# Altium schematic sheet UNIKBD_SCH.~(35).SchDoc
size A4
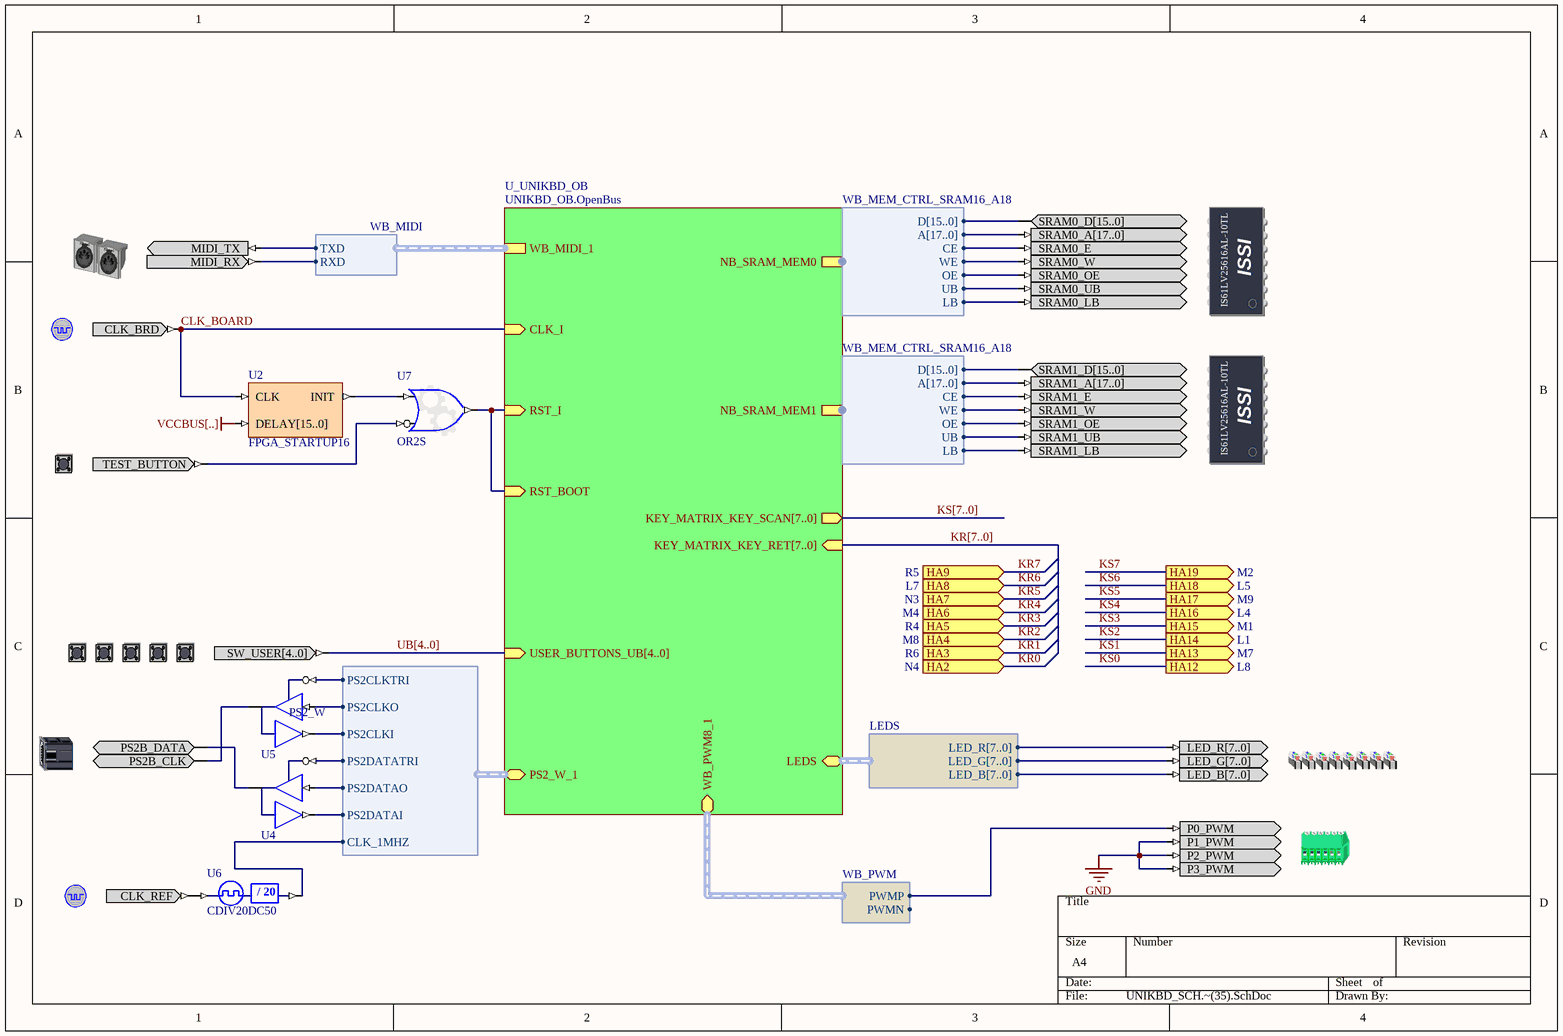
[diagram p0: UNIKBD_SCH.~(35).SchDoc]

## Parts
(Parts that share a designator on the sheet are numbered #1, #2 ... from top to bottom, then left to right.)
?#1  SRAM0  (value not drawn)
?#2  MIDI  (value not drawn)
?#3  CLOCK_BOARD  (value not drawn)
?#4  SRAM1  (value not drawn)
?#5  TEST_BUTTON  (value not drawn)
?#6  USER_BUTTONS  (value not drawn)
?#7  LEDS_RGB  (value not drawn)
?#8  PS2B  (value not drawn)
?#9  PWM  (value not drawn)
?#10  CLOCK_REFERENCE  (value not drawn)
U2  FPGA_STARTUP16
U4  IOBUF  (value not drawn)
U5  IOBUF  (value not drawn)
U6  CDIV20DC50
U7  OR2S

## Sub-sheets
U_UNIKBD_OB = UNIKBD_OB.OpenBus: KEY_MATRIX_KEY_SCAN[7..0] (out), KEY_MATRIX_KEY_RET[7..0] (in), WB_MIDI_1 (harness WB_MIDI), NB_SRAM_MEM0 (harness WB_MEM_CTRL_SRAM16_A18), NB_SRAM_MEM1 (harness WB_MEM_CTRL_SRAM16_A18), RST_I (in), CLK_I (in), USER_BUTTONS_UB[4..0] (in), PS2_W_1 (harness PS2_W), LEDS (harness LEDS), WB_PWM8_1 (harness WB_PWM), RST_BOOT (in)

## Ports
HA2 (in, see N4), HA3 (in, see R6), HA4 (in, see M8), HA5 (in, see R4), HA6 (in, see M4), HA7 (in, see N3), HA8 (in, see L7), HA9 (in, see R5), HA12 (out, see L8), HA13 (out, see M7), HA14 (out, see L1), HA15 (out, see M1), HA16 (out, see L4), HA17 (out, see M9), HA18 (out, see L5), HA19 (out, see M2)

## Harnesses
WB_MEM_CTRL_SRAM16_A18: D[15..0], A[17..0], CE, WE, OE, UB, LB
WB_MIDI: RXD, TXD
LEDS: LED_R[7..0], LED_G[7..0], LED_B[7..0]
PS2_W: PS2CLKTRI, PS2CLKO, PS2CLKI, PS2DATATRI, PS2DATAO, PS2DATAI, CLK_1MHZ
WB_PWM: PWMN, PWMP

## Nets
GND: ?#9.P1_PWM ?#9.P2_PWM ?#9.P3_PWM
VCCBUS[..]: U2.DELAY[15..0]
CLK_BOARD: ?#3.CLK_BRD U2.CLK ; sheet U_UNIKBD_OB/CLK_I
Net?#1_SRAM0_E: ?#1.SRAM0_E ; sheet U_UNIKBD_OB/NB_SRAM_MEM0.CE
Net?#1_SRAM0_LB: ?#1.SRAM0_LB ; sheet U_UNIKBD_OB/NB_SRAM_MEM0.LB
Net?#1_SRAM0_OE: ?#1.SRAM0_OE ; sheet U_UNIKBD_OB/NB_SRAM_MEM0.OE
Net?#1_SRAM0_UB: ?#1.SRAM0_UB ; sheet U_UNIKBD_OB/NB_SRAM_MEM0.UB
Net?#1_SRAM0_W: ?#1.SRAM0_W ; sheet U_UNIKBD_OB/NB_SRAM_MEM0.WE
Net?#2_MIDI_RX: ?#2.MIDI_RX ; sheet U_UNIKBD_OB/WB_MIDI_1.RXD
Net?#2_MIDI_TX: ?#2.MIDI_TX ; sheet U_UNIKBD_OB/WB_MIDI_1.TXD
Net?#4_SRAM1_E: ?#4.SRAM1_E ; sheet U_UNIKBD_OB/NB_SRAM_MEM1.CE
Net?#4_SRAM1_LB: ?#4.SRAM1_LB ; sheet U_UNIKBD_OB/NB_SRAM_MEM1.LB
Net?#4_SRAM1_OE: ?#4.SRAM1_OE ; sheet U_UNIKBD_OB/NB_SRAM_MEM1.OE
Net?#4_SRAM1_UB: ?#4.SRAM1_UB ; sheet U_UNIKBD_OB/NB_SRAM_MEM1.UB
Net?#4_SRAM1_W: ?#4.SRAM1_W ; sheet U_UNIKBD_OB/NB_SRAM_MEM1.WE
Net?#5_TEST_BUTTON: ?#5.TEST_BUTTON U7.I1
Net?#8_PS2B_CLK: ?#8.PS2B_CLK U5.IO
Net?#8_PS2B_DATA: ?#8.PS2B_DATA U4.IO
Net?#9_P0_PWM: ?#9.P0_PWM ; sheet U_UNIKBD_OB/WB_PWM8_1.PWMP
Net?#10_CLK_REF: ?#10.CLK_REF U6.CLKIN
NetU2_INIT: U2.INIT U7.I0
NetU4_I: U4.I ; sheet U_UNIKBD_OB/PS2_W_1.PS2DATAO
NetU4_O: U4.O ; sheet U_UNIKBD_OB/PS2_W_1.PS2DATAI
NetU4_T: U4.T ; sheet U_UNIKBD_OB/PS2_W_1.PS2DATATRI
NetU5_I: U5.I ; sheet U_UNIKBD_OB/PS2_W_1.PS2CLKO
NetU5_O: U5.O ; sheet U_UNIKBD_OB/PS2_W_1.PS2CLKI
NetU5_T: U5.T ; sheet U_UNIKBD_OB/PS2_W_1.PS2CLKTRI
NetU6_CLKDV: U6.CLKDV ; sheet U_UNIKBD_OB/PS2_W_1.CLK_1MHZ
NetU7_O: U7.O ; sheet U_UNIKBD_OB/RST_I, sheet U_UNIKBD_OB/RST_BOOT

Not connected (* = marked no-connect by the designer): ?#1 SRAM0_A[17..0] SRAM0_D[15..0]; ?#4 SRAM1_A[17..0] SRAM1_D[15..0]; ?#6 SW_USER[4..0]; ?#7 LED_B[7..0] LED_G[7..0] LED_R[7..0]

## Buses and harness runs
bus KR[7..0] = sheet U_UNIKBD_OB/KEY_MATRIX_KEY_RET[7..0]
bus KS[7..0] = sheet U_UNIKBD_OB/KEY_MATRIX_KEY_SCAN[7..0]
bus UB[4..0] = sheet U_UNIKBD_OB/USER_BUTTONS_UB[4..0]

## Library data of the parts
?#1 = SRAM0: Free Static RAM - Daughterboard; PortComponent: True
?#2 = MIDI: MIDI Connector; PortComponent: True
?#3 = CLOCK_BOARD: Global System Clock Supply; PortComponent: True
?#4 = SRAM1: Free Static RAM - Daughterboard; PortComponent: True
?#5 = TEST_BUTTON: Test / Reset Button; PortComponent: True
?#6 = USER_BUTTONS: Generic User Buttons; PortComponent: True
?#7 = LEDS_RGB: LEDS RGB; PortComponent: True
?#8 = PS2B: Key Board PS2 Connector; PortComponent: True
?#9 = PWM: Pulse Width Modulation; PortComponent: True
?#10 = CLOCK_REFERENCE: Global System Clock Reference Supply; PortComponent: True
U2 = FPGA_STARTUP16: FPGA Startup With 16 Bit Delay
U4 U5 = IOBUF: Input/Output Buffer; Enable: Low; Control: Common Control T; ArchiveName: GENERIC; VHDLIB_SIM: GENERIC_LIB
U6 = CDIV20DC50: Clock Divider by 20 with 50% Duty Cycle Output; DivisorRate: 20; DutyCycle: 50; ArchiveName: GENERIC; VHDLIB_SIM: GENERIC_LIB
U7 = GATE: Configurable Generic Gate; ConfiguratorName: GENERIC_GATE; ConfigurationParameters: {}Version[1.0]{}GateKind[OR]{}BusInput[False]{}GateInputType[Bit]{}GateOutputOption[Normal]{}BusWidth[8]{}RegisterOutputs[False]{}NegativeClockEdge[False]{}InputCount[2]{}InputInvert0[False]{}InputInvert1[True]{}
